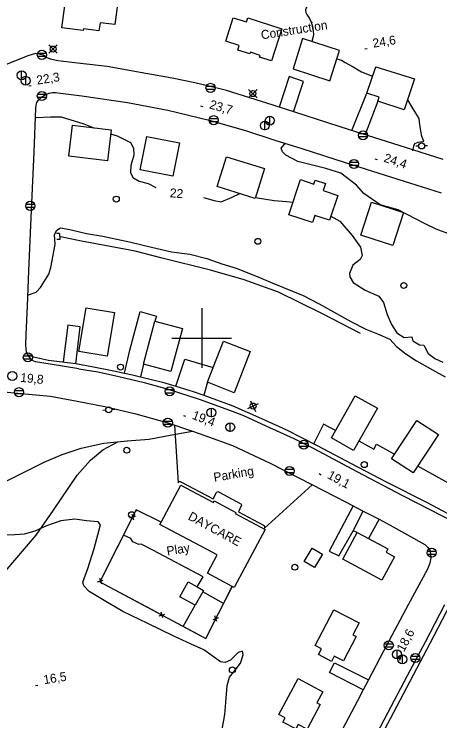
# Model space of a CAD drawing. Extents: x 646142 to 649934, y 5874075 to 5876351.
# Drawn here: x 647137.1 to 647279.9, y 5875071.6 to 5875308.6 of the extents above; entities that cross this region are included whole.
import ezdxf

# ---------------------------------------------------------------- set-up
doc = ezdxf.new("R2010")
doc.units = 0
for name, color, linetype in [('Niveau 1', 7, 'Continuous'), ('Niveau 19', 7, 'Continuous'), ('Niveau 2', 7, 'Continuous'), ('Niveau 21', 7, 'Continuous'), ('Niveau 22', 7, 'Continuous'), ('Niveau 26', 7, 'Continuous'), ('Niveau 3', 7, 'Continuous'), ('Niveau 31', 7, 'Continuous'), ('Niveau 36', 7, 'Continuous'), ('Niveau 37', 7, 'Continuous'), ('Niveau 4', 7, 'Continuous'), ('Niveau 52', 7, 'Continuous'), ('Niveau 56', 7, 'Continuous'), ('Niveau 61', 7, 'Continuous')]:
    doc.layers.add(name, color=color, linetype=linetype)

msp = doc.modelspace()

# ---------------------------------------------------------------- linework, layer by layer
at = {"layer": 'Niveau 1'}
msp.add_lwpolyline([(647141.45, 5875214.48), (647141.95, 5875214.49), (647144.48, 5875215.37), (647145.91, 5875216.98), (647148.71, 5875221.37), (647149.38, 5875223.68), (647150.8, 5875231.33), (647150.67, 5875234.68), (647151.43, 5875236.2), (647152.67, 5875236.92), (647155.81, 5875236.39), (647161.32, 5875235.07), (647166.84, 5875234.15), (647176.18, 5875232.21), (647183.16, 5875230.44), (647189.88, 5875228.93), (647196.07, 5875228.09), (647201.7, 5875226.72), (647206.79, 5875224.9), (647211.57, 5875223.43), (647218.59, 5875220.64), (647223.89, 5875218.44), (647234.08, 5875214.22), (647239.38, 5875211.51), (647250.03, 5875205.53), (647255.08, 5875202.96), (647259.01, 5875201.39), (647263.06, 5875199.61), (647265.31, 5875197.16), (647268.51, 5875194.66), (647272.04, 5875192.33), (647277.43, 5875189.34), (647281.7, 5875187.04)], dxfattribs=at)
at = {"layer": 'Niveau 19'}
for points in [[(647230.81, 5875275.89), (647234.09, 5875286.09), (647229.35, 5875287.67), (647225.99, 5875277.44)], [(647250.38, 5875269.62), (647255.44, 5875282.18)], [(647259.08, 5875279.41), (647254.81, 5875268.22)], [(647174.14, 5875188.23), (647175.91, 5875195.88), (647179.34, 5875208.88), (647184.82, 5875207.39), (647184.31, 5875205.69)], [(647157.82, 5875191.4), (647159.2, 5875203.8), (647155.14, 5875204.35), (647153.5, 5875191.98)], [(647191.36, 5875183.84), (647194.37, 5875192.95), (647203.83, 5875190.09)], [(647180.46, 5875191.25), (647179.48, 5875187)], [(647201.91, 5875185.15), (647200.76, 5875180.79)], [(647244.91, 5875168.99), (647240.82, 5875171.13), (647237.6, 5875164.59)], [(647252.71, 5875165.47), (647257.71, 5875162.74), (647258.59, 5875164.42), (647264.69, 5875161.07)], [(647272.44, 5875157.09), (647282.46, 5875151.51)], [(647250.81, 5875143.7), (647242.77, 5875128.47), (647245.97, 5875126.97), (647250.8, 5875135.36)], [(647252.13, 5875134.8), (647250.8, 5875135.36), (647254.2, 5875141.95)], [(647259.48, 5875139.23), (647256, 5875132.72)], [(647254.19, 5875082.02), (647242.92, 5875087.82), (647244.57, 5875091.09), (647255.97, 5875085.4)]]:
    msp.add_lwpolyline(points, dxfattribs=at)
at = {"layer": 'Niveau 2'}
for points in [[(647235.63, 5875311.32), (647235.08, 5875310.72), (647234.87, 5875310.03), (647234.95, 5875309.22), (647235.22, 5875308.48), (647236.17, 5875307.13), (647236.77, 5875305.99), (647237.06, 5875304.58), (647237.42, 5875302.98), (647237.54, 5875301.84), (647237.37, 5875301.19), (647236.92, 5875299.42)], [(647245.35, 5875293.67), (647246.84, 5875293.2), (647248.17, 5875292.47), (647250.79, 5875290.92), (647253.55, 5875289.32), (647257.34, 5875287.86)], [(647269.05, 5875279.88), (647270.46, 5875277.38), (647271.67, 5875275.44), (647272.78, 5875273.58), (647272.95, 5875272.39), (647273.23, 5875270.16), (647273.58, 5875268.13), (647273.85, 5875267.43), (647274.37, 5875266.09), (647274.16, 5875265.78), (647272.45, 5875265.56), (647271.39, 5875265.11), (647271.03, 5875264.4), (647270.72, 5875262.78)], [(647144.18, 5875274.06), (647144.42, 5875274.01), (647149.26, 5875274.23), (647152.85, 5875274.14), (647160.49, 5875271.9), (647163.83, 5875270.5)], [(647169.43, 5875268.52), (647171.61, 5875267.77), (647176.12, 5875265.55), (647177.11, 5875263.7), (647177.29, 5875261.36), (647176.2, 5875257.92), (647176.15, 5875255.56), (647176.9, 5875253.8), (647179.04, 5875252.64), (647182.08, 5875251.81), (647184.59, 5875250.44)], [(647283.47, 5875234.76), (647278.6, 5875236.51), (647274.73, 5875238.39), (647265.85, 5875242.95), (647259.86, 5875244.67), (647254.34, 5875248.51), (647251.93, 5875251.23), (647246.68, 5875255.27), (647241.61, 5875256.91), (647232.21, 5875259.25), (647228.19, 5875261.29), (647227.09, 5875262.5), (647226.68, 5875263.71), (647227.87, 5875265.1), (647228.22, 5875265.31)], [(647200.55, 5875247.17), (647204.22, 5875246.1), (647206.52, 5875245.71), (647210.18, 5875247.24), (647212.77, 5875248.44)], [(647218.05, 5875247.18), (647224.34, 5875246.08), (647228.47, 5875245.83), (647230.64, 5875245.62)], [(647243.37, 5875240.93), (647246.35, 5875239.16), (647250.52, 5875234.43), (647253.28, 5875230.53), (647253.85, 5875227.73), (647253.18, 5875226.39), (647250.71, 5875224.47), (647249.56, 5875221.6), (647249.67, 5875220.52), (647250.84, 5875218.64), (647254.85, 5875216.08), (647259.38, 5875214.03), (647260.98, 5875211.96), (647262.25, 5875207.86), (647263.68, 5875204.57), (647265.46, 5875201.72), (647267.87, 5875200.14), (647270.44, 5875200.46), (647270.81, 5875199.07), (647273.02, 5875197.76), (647274.54, 5875197.57), (647275.96, 5875194.86), (647278.22, 5875193.09), (647280.93, 5875191.89)], [(647206.29, 5875065.53), (647207.74, 5875073.69), (647208.15, 5875077.71), (647208.5, 5875083.51), (647209.33, 5875086.3), (647211.19, 5875088.62), (647212.98, 5875090.99), (647213.93, 5875093.73), (647213.69, 5875094.98), (647212.22, 5875094.54), (647209.63, 5875091.98), (647207.85, 5875091.17), (647206.32, 5875091.42), (647200.69, 5875095.42), (647196.43, 5875097.3), (647190.7, 5875100.02), (647181.98, 5875104.22), (647173.56, 5875108.29), (647167.27, 5875111.93), (647162.27, 5875114.94), (647160.45, 5875116.84), (647160.1, 5875118.07), (647161.79, 5875122.67), (647163.91, 5875129.39), (647166.08, 5875137.32), (647165.28, 5875138.33), (647161.35, 5875138.69), (647157.47, 5875139.23), (647152.77, 5875138.64), (647147.94, 5875137.02), (647143.99, 5875135.24), (647140.43, 5875134.26), (647137.32, 5875134.01), (647133.33, 5875133.9)]]:
    msp.add_lwpolyline(points, dxfattribs=at)
at = {"layer": 'Niveau 21'}
for points in [[(647280.95, 5875259.87), (647268.4, 5875263.92), (647249.6, 5875269.87), (647223.95, 5875278.09), (647208.28, 5875282.97), (647202, 5875284.58), (647197.71, 5875285.58), (647190.14, 5875287.11), (647181.3, 5875288.75), (647168.25, 5875291.06), (647159.33, 5875292.11), (647151.73, 5875292.97), (647149.26, 5875293.53), (647147.95, 5875294.12), (647146.9, 5875294.92), (647144.2, 5875295.46), (647141.73, 5875294.63), (647134.18, 5875291.64)], [(647158.78, 5875189.64), (647149.22, 5875191.26), (647144.27, 5875192.03), (647143.66, 5875192.25), (647142.91, 5875192.73), (647142.34, 5875193.42), (647141.57, 5875194.5), (647141.21, 5875195.4), (647141.07, 5875196.33), (647141.03, 5875197.68), (647141.15, 5875201.14), (647141.54, 5875210.69), (647142.04, 5875222.49), (647142.9, 5875242.92), (647143.77, 5875262.3), (647144.34, 5875277.13), (647144.48, 5875278.1), (647144.73, 5875278.97), (647145.16, 5875279.67), (647145.66, 5875280.2), (647146.39, 5875280.85), (647147.41, 5875281.51), (647148.25, 5875281.96), (647148.86, 5875282.14), (647149.97, 5875282.31), (647150.94, 5875282.31), (647152.66, 5875282.18), (647159.82, 5875281.25), (647175.1, 5875279.05), (647188.63, 5875276.48), (647202.51, 5875273.12), (647214.65, 5875269.56), (647224.54, 5875266.35), (647233.55, 5875263.52), (647245.04, 5875259.9), (647257.33, 5875255.99), (647269.75, 5875252.06), (647280.31, 5875248.67)], [(647158.78, 5875189.64), (647165.19, 5875188.63), (647171.81, 5875187.26), (647180.72, 5875185.09), (647188.7, 5875182.83), (647199.47, 5875179.37), (647210.17, 5875175.45), (647214.02, 5875174.01), (647221.54, 5875170.56), (647230.88, 5875166.26), (647237.58, 5875162.95), (647252, 5875155.29), (647267.38, 5875147.16), (647285.42, 5875137.94), (647296.39, 5875132.22), (647308.36, 5875125.81), (647322.73, 5875118.39), (647329.68, 5875114.76), (647338.75, 5875110.68), (647353.4, 5875105.02), (647362.11, 5875102.16), (647373.66, 5875098.57), (647386.89, 5875095.51)], [(647129.03, 5875182.41), (647139.45, 5875181.45), (647149.3, 5875180.46), (647158.27, 5875178.82), (647167.49, 5875177.08), (647177.91, 5875174.62), (647188.27, 5875171.72), (647196.92, 5875168.76), (647201.1, 5875167.33), (647210.35, 5875163.95), (647222.98, 5875158.05), (647236.89, 5875150.91), (647248.48, 5875144.9)], [(647248.48, 5875144.9), (647254.2, 5875141.95), (647259.48, 5875139.23), (647263.23, 5875137.29), (647274.88, 5875130.72), (647275.89, 5875129.79), (647276.59, 5875128.61), (647276.82, 5875126.34), (647276.54, 5875124.47), (647275.7, 5875122.44), (647269.27, 5875110.52), (647261, 5875094.98), (647255.97, 5875085.4), (647254.19, 5875082.02), (647252.27, 5875078.35), (647246.24, 5875066.95)], [(647404.42, 5874995.61), (647383.56, 5874999.21), (647359.7, 5875003.67), (647349.49, 5875005.67), (647330.62, 5875009.23), (647326.93, 5875010.02), (647321.05, 5875011.75), (647311.59, 5875015.56), (647297.2, 5875023.14), (647280.31, 5875032.56), (647266.62, 5875040.33), (647257.64, 5875045.21), (647254.67, 5875046.99), (647253.59, 5875048.5), (647252.7, 5875050.38), (647252.15, 5875052.4), (647252.44, 5875054.16), (647253.13, 5875056.53), (647257.52, 5875064.93), (647262.38, 5875074.29), (647269.02, 5875086.82), (647275.09, 5875098.14), (647281.6, 5875110.65)]]:
    msp.add_lwpolyline(points, dxfattribs=at)
at = {"layer": 'Niveau 22'}
for points in [[(647141.57, 5875194.5), (647143.63, 5875193.71), (647148.61, 5875192.63), (647157.77, 5875191.41), (647163.19, 5875190.49), (647169.93, 5875189.13), (647174.14, 5875188.23), (647176.79, 5875187.67), (647179.48, 5875187), (647186.89, 5875185.17), (647191.36, 5875183.84), (647197.15, 5875182.12), (647200.76, 5875180.79), (647210.49, 5875177.21), (647220.05, 5875173.05), (647228.18, 5875169.31), (647238.78, 5875164), (647250.15, 5875157.97), (647261.87, 5875151.75), (647275.39, 5875144.92), (647287.59, 5875138.52)], [(647133.12, 5875151.38), (647140.41, 5875155.06), (647147.15, 5875158.35), (647153.15, 5875160.89), (647159.52, 5875163.1), (647167.2, 5875164.73), (647174.95, 5875165.54), (647182.37, 5875166.1), (647189.93, 5875167.59), (647196.92, 5875168.76)], [(647046.91, 5875074.33), (647057.34, 5875080.28), (647062.95, 5875083.1), (647072.61, 5875087.23), (647091.51, 5875094.75), (647105.67, 5875100.32), (647110.9, 5875103.1), (647117.34, 5875107.37), (647126.43, 5875113.96), (647134.04, 5875121.74), (647144.5, 5875133.85), (647150.3, 5875142.29), (647158.18, 5875154.03), (647162.7, 5875159.04), (647166.79, 5875162.46), (647171.92, 5875165.22)], [(647257.93, 5875062.33), (647263.3, 5875072.43), (647269.94, 5875084.97), (647276.68, 5875097.62), (647282.12, 5875108.18), (647287.6, 5875118.28), (647286.71, 5875120.03)]]:
    msp.add_lwpolyline(points, dxfattribs=at)
at = {"layer": 'Niveau 26'}
for p, q in [((647152.33, 5875235.06), (647151.33, 5875235.04)), ((647152.33, 5875235.06), (647152.37, 5875233.04)), ((647152.37, 5875233.04), (647151.38, 5875233.02))]:
    msp.add_line(p, q, dxfattribs=at)
at = {"layer": 'Niveau 3'}
for p, q in [((647254.73, 5875296.96), (647255.52, 5875297.09)), ((647141.98, 5875284.57), (647142.77, 5875284.7)), ((647199.61, 5875277.9), (647200.37, 5875277.68)), ((647258.08, 5875260.14), (647258.84, 5875259.89)), ((647193.86, 5875174.04), (647194.61, 5875173.76)), ((647239.38, 5875154.55), (647240.08, 5875154.16)), ((647266.4, 5875092), (647266.78, 5875092.7)), ((647144.29, 5875083.49), (647145.08, 5875083.61))]:
    msp.add_line(p, q, dxfattribs=at)
at = {"layer": 'Niveau 31'}
for points in [[(647153.13, 5875304.08), (647155.83, 5875324.69), (647168.29, 5875323.05), (647167.14, 5875314.26), (647171.95, 5875313.62), (647170.83, 5875305.12), (647165.89, 5875305.77), (647165.52, 5875302.99), (647160.3, 5875303.67), (647160.23, 5875303.15), (647153.13, 5875304.08)], [(647226.89, 5875303.71), (647223.45, 5875292.96), (647219.42, 5875294.25), (647219.6, 5875294.8), (647216.33, 5875295.85), (647216.15, 5875295.27), (647212.09, 5875296.56), (647212.6, 5875298.14), (647208.05, 5875299.59), (647210.56, 5875307.45), (647215.04, 5875306.02), (647215.46, 5875307.36), (647226.89, 5875303.71)], [(647230.64, 5875290.33), (647242.93, 5875286.25), (647246.25, 5875296.43), (647233.82, 5875300.42), (647230.64, 5875290.33), (647230.64, 5875290.33)], [(647258.39, 5875290.99), (647271.35, 5875286.94), (647267.95, 5875276.52), (647259.08, 5875279.41), (647259.54, 5875280.78), (647255.44, 5875282.18), (647258.39, 5875290.99), (647258.39, 5875290.99)], [(647168.35, 5875259.46), (647155.39, 5875261.01), (647156.63, 5875271.36), (647169.59, 5875269.81), (647168.35, 5875259.46)], [(647190.34, 5875254.27), (647179.41, 5875256.44), (647181.63, 5875267.63), (647192.56, 5875265.46), (647190.34, 5875254.27)], [(647217.94, 5875246.82), (647205.17, 5875250.81), (647208.29, 5875260.8), (647221.06, 5875256.81), (647217.94, 5875246.82)], [(647229.22, 5875241.35), (647233.13, 5875253.12), (647237.66, 5875251.62), (647238.1, 5875252.95), (647241.48, 5875251.82), (647240.71, 5875249.49), (647245.67, 5875247.85), (647242.89, 5875239.49), (647237.97, 5875241.12), (647237.17, 5875238.71), (647229.22, 5875241.35)], [(647264.16, 5875231.04), (647253.37, 5875234.52), (647256.92, 5875245.54), (647267.71, 5875242.06), (647264.16, 5875231.04)], [(647158.79, 5875195.44), (647161.23, 5875210.13), (647170.73, 5875208.56), (647168.29, 5875193.87), (647158.79, 5875195.44)], [(647180.46, 5875191.25), (647184.31, 5875205.69), (647193.55, 5875203.23), (647189.7, 5875188.79), (647180.46, 5875191.25)], [(647201.91, 5875185.15), (647203.83, 5875190.09), (647207.27, 5875198.94), (647216.21, 5875195.47), (647210.85, 5875181.68), (647201.91, 5875185.15)], [(647243.5, 5875166.5), (647251.53, 5875180.67), (647258.94, 5875176.47), (647250.91, 5875162.3), (647243.5, 5875166.5)], [(647263.67, 5875159.53), (647272.18, 5875172.38), (647279.4, 5875167.6), (647270.89, 5875154.75), (647263.67, 5875159.53)], [(647205.19, 5875127.29), (647186.01, 5875137.5), (647186.44, 5875138.29), (647193.02, 5875150.67), (647203.95, 5875144.86), (647204.22, 5875145.35), (647211.43, 5875141.52), (647211.22, 5875141.11), (647221.25, 5875135.78), (647210.92, 5875116.37), (647210.27, 5875116.71), (647201.93, 5875121.15), (647205.19, 5875127.29)], [(647260.46, 5875118.78), (647247.32, 5875125.85), (647252.13, 5875134.8), (647256, 5875132.72), (647262.42, 5875129.27), (647261.83, 5875128.18), (647264.69, 5875126.64), (647260.46, 5875118.78)], [(647234.35, 5875125.1), (647237.01, 5875129.57), (647240.49, 5875127.49), (647237.83, 5875123.02), (647234.35, 5875125.1)], [(647195.47, 5875118.25), (647198.49, 5875116.55), (647200.61, 5875115.36), (647200.33, 5875114.86), (647197.8, 5875110.36), (647192.67, 5875113.24), (647195.47, 5875118.25)], [(647238.07, 5875096.88), (647244.33, 5875108.86), (647252.8, 5875104.44), (647250.74, 5875100.5), (647251.83, 5875099.94), (647247.52, 5875091.7), (647244.47, 5875093.29), (647243.57, 5875091.56), (647239.15, 5875093.87), (647240.15, 5875095.79), (647238.07, 5875096.88)], [(647225.92, 5875073.74), (647232.35, 5875085.8), (647240.64, 5875081.39), (647238.67, 5875077.69), (647239.78, 5875077.1), (647235.36, 5875068.81), (647232.33, 5875070.43), (647231.52, 5875068.92), (647227.24, 5875071.2), (647228, 5875072.63), (647225.92, 5875073.74)]]:
    msp.add_lwpolyline(points, dxfattribs=at)
at = {"layer": 'Niveau 36'}
for p, q in [((647151.56, 5875295.51), (647148.74, 5875298.33)), ((647148.74, 5875295.51), (647151.56, 5875298.33)), ((647147.82, 5875295.44), (647144.94, 5875295.44)), ((647144.94, 5875294.52), (647147.82, 5875294.52)), ((647139.61, 5875286.61), (647139.61, 5875289.61)), ((647140.96, 5875284.78), (647140.96, 5875287.78)), ((647204.4, 5875284.37), (647201.52, 5875284.37)), ((647201.52, 5875283.45), (647204.4, 5875283.45)), ((647218.57, 5875280.57), (647215.75, 5875283.39)), ((647215.75, 5875280.57), (647218.57, 5875283.39)), ((647147.82, 5875281.67), (647144.94, 5875281.67)), ((647144.94, 5875280.75), (647147.82, 5875280.75)), ((647205.47, 5875273.53), (647202.59, 5875273.53)), ((647202.59, 5875272.61), (647205.47, 5875272.61)), ((647221.18, 5875269.77), (647221.18, 5875272.77)), ((647222.85, 5875271.43), (647222.85, 5875274.43)), ((647255.55, 5875268.48), (647252.67, 5875268.48)), ((647252.67, 5875267.56), (647255.55, 5875267.56)), ((647271.78, 5875264.43), (647272.78, 5875264.43)), ((647275.78, 5875264.43), (647274.78, 5875264.43)), ((647252.5, 5875258.85), (647249.62, 5875258.85)), ((647249.62, 5875257.93), (647252.5, 5875257.93)), ((647143.94, 5875244.79), (647141.06, 5875244.79)), ((647141.06, 5875243.87), (647143.94, 5875243.87)), ((647143.13, 5875193.97), (647140.25, 5875193.97)), ((647140.25, 5875193.05), (647143.13, 5875193.05)), ((647190.69, 5875182.59), (647187.81, 5875182.59)), ((647140.14, 5875182.29), (647137.26, 5875182.29)), ((647137.26, 5875181.37), (647140.14, 5875181.37)), ((647187.81, 5875181.67), (647190.69, 5875181.67)), ((647215.44, 5875176.33), (647219.04, 5875178.05)), ((647216.39, 5875178.99), (647218.1, 5875175.39)), ((647166.81, 5875175.83), (647167.81, 5875175.88)), ((647170.81, 5875176.02), (647169.81, 5875175.98)), ((647203.24, 5875173.51), (647203.24, 5875176.51)), ((647190.08, 5875172.03), (647187.2, 5875172.03)), ((647187.2, 5875171.11), (647190.08, 5875171.11)), ((647209.57, 5875168.6), (647209.57, 5875171.6)), ((647235.68, 5875164.66), (647232.8, 5875164.66)), ((647232.8, 5875163.74), (647235.68, 5875163.74)), ((647230.9, 5875155.87), (647228.02, 5875155.87)), ((647228.02, 5875154.95), (647230.9, 5875154.95)), ((647278.59, 5875128.46), (647275.71, 5875128.46)), ((647275.71, 5875127.54), (647278.59, 5875127.54)), ((647264.2, 5875097.36), (647261.32, 5875097.36)), ((647261.32, 5875096.44), (647264.2, 5875096.44)), ((647265.52, 5875092.38), (647265.52, 5875095.38)), ((647267.31, 5875090.72), (647267.31, 5875093.72)), ((647273.1, 5875093.17), (647270.22, 5875093.17)), ((647270.22, 5875092.25), (647273.1, 5875092.25))]:
    msp.add_line(p, q, dxfattribs=at)
for centre, radius in [((647146.38, 5875294.99), 1.52), ((647150.15, 5875296.93), 1), ((647139.6, 5875288.12), 1.5), ((647140.95, 5875286.28), 1.5), ((647202.96, 5875283.91), 1.52), ((647146.38, 5875281.21), 1.52), ((647217.17, 5875281.98), 1), ((647204.03, 5875273.07), 1.52), ((647221.17, 5875271.28), 1.5), ((647222.84, 5875272.94), 1.5), ((647254.11, 5875268.02), 1.52), ((647273.78, 5875264.43), 1), ((647251.06, 5875258.4), 1.52), ((647171.35, 5875246.6), 1), ((647142.5, 5875244.34), 1.52), ((647218.83, 5875232.44), 1), ((647267.78, 5875217.64), 1), ((647141.69, 5875193.51), 1.52), ((647172.77, 5875190.26), 1), ((647136.45, 5875187.26), 1.5), ((647138.7, 5875181.84), 1.52), ((647189.25, 5875182.14), 1.52), ((647217.25, 5875177.19), 1), ((647168.81, 5875175.93), 1), ((647203.23, 5875175.02), 1.5), ((647188.64, 5875171.58), 1.52), ((647209.56, 5875170.11), 1.5), ((647234.24, 5875164.21), 1.52), ((647174.87, 5875162.37), 1), ((647229.46, 5875155.42), 1.52), ((647254.53, 5875157.54), 1), ((647176.47, 5875140.76), 1), ((647277.15, 5875128.01), 1.52), ((647231.22, 5875123.13), 1), ((647262.76, 5875096.91), 1.52), ((647265.51, 5875093.89), 1.5), ((647267.3, 5875092.23), 1.5), ((647271.66, 5875092.72), 1.52), ((647210.29, 5875088.7), 1)]:
    msp.add_circle(centre, radius, dxfattribs=at)
at = {"layer": 'Niveau 37'}
for points in [[(647186.44, 5875138.29), (647178.05, 5875142.36), (647165.86, 5875118.18), (647201.35, 5875099.28), (647210.27, 5875116.71)], [(647186.44, 5875138.29), (647178.05, 5875142.36), (647165.86, 5875118.18), (647201.35, 5875099.28), (647210.27, 5875116.71)], [(647186.44, 5875138.29), (647178.05, 5875142.36), (647165.86, 5875118.18), (647201.35, 5875099.28), (647210.27, 5875116.71)], [(647186.44, 5875138.29), (647178.05, 5875142.36), (647177.74, 5875141.76)], [(647175.89, 5875139.66), (647177.79, 5875140.28)], [(647176.53, 5875140.92), (647177.16, 5875139.02)], [(647175.94, 5875138.18), (647171.44, 5875129.25)], [(647171.44, 5875129.25), (647166.94, 5875120.32)], [(647165.09, 5875118.22), (647166.99, 5875118.85)], [(647165.73, 5875119.49), (647166.35, 5875117.59)], [(647167.26, 5875117.43), (647176.09, 5875112.73)], [(647205.62, 5875107.63), (647210.18, 5875116.53)], [(647210.18, 5875116.53), (647210.27, 5875116.71)], [(647176.09, 5875112.73), (647184.92, 5875108.03)], [(647193.82, 5875103.28), (647197.8, 5875110.36)], [(647193.82, 5875103.28), (647197.8, 5875110.36)], [(647193.82, 5875103.28), (647197.8, 5875110.36)], [(647193.82, 5875103.28), (647197.8, 5875110.36)], [(647185.72, 5875106.79), (647187.64, 5875107.38)], [(647186.97, 5875106.13), (647186.39, 5875108.04)], [(647205.02, 5875104.89), (647204.4, 5875106.8)], [(647188.45, 5875106.15), (647197.27, 5875101.45)], [(647205.67, 5875106.15), (647203.76, 5875105.54)], [(647197.27, 5875101.45), (647201.35, 5875099.28), (647203.8, 5875104.07)]]:
    msp.add_lwpolyline(points, dxfattribs=at)
at = {"layer": 'Niveau 4'}
msp.add_lwpolyline([(647253.23, 5875201.53), (647240.56, 5875208.14), (647225.75, 5875215.41), (647214.22, 5875219.48), (647202.96, 5875222.77), (647186.79, 5875226.84), (647177.71, 5875229.1), (647167.51, 5875231.04), (647159.68, 5875232.45), (647152.63, 5875233.9)], dxfattribs=at)
at = {"layer": 'Niveau 52'}
msp.add_lwpolyline([(647190.87, 5875170.83), (647192.12, 5875151.45), (647192.35, 5875151.77), (647192.59, 5875151.86), (647192.73, 5875151.85), (647193, 5875151.83), (647203.83, 5875146.09), (647204.94, 5875148.21), (647205.14, 5875148.4), (647205.42, 5875148.48), (647205.59, 5875148.47), (647205.87, 5875148.33), (647213.09, 5875144.44), (647213.27, 5875144.26), (647213.34, 5875144.05), (647213.32, 5875143.81), (647213.28, 5875143.68), (647212.31, 5875141.7), (647220.78, 5875137.28), (647221.02, 5875137.04), (647221.08, 5875136.76), (647221.04, 5875136.44), (647221.01, 5875136.27), (647237.09, 5875150.8)], dxfattribs=at)
at = {"layer": 'Niveau 56'}
for points in [[(647198.49, 5875116.55), (647200.48, 5875119.86), (647183.57, 5875128.88), (647179.66, 5875130.91), (647178.87, 5875130.71), (647176.92, 5875131.67), (647176.23, 5875132.75), (647173.76, 5875133.86)], [(647207.33, 5875110.96), (647200.33, 5875114.86)]]:
    msp.add_lwpolyline(points, dxfattribs=at)
at = {"layer": 'Niveau 61'}
for points in [[(647200, 5875210), (647200, 5875200), (647200, 5875190)], [(647190, 5875200), (647200, 5875200), (647210, 5875200)]]:
    msp.add_lwpolyline(points, dxfattribs=at)

# ---------------------------------------------------------------- texts
at = {"layer": 'Niveau 2'}
msp.add_text('22', height=3, rotation=355.3665, dxfattribs=at).set_placement((647189.22, 5875247.25))
at = {"layer": 'Niveau 3'}
for s, rotation, p in [('24,6 ', 8.9405, (647257.58, 5875297.37)), ('22,3 ', 8.9405, (647144.83, 5875284.98)), ('23,7 ', 343.9857, (647202.36, 5875277.07)), ('24,4 ', 341.6166, (647260.81, 5875259.2)), ('19,8 ', 354.4811, (647139.05, 5875185.33)), ('19,4 ', 339.2247, (647196.54, 5875172.98)), ('19,1 ', 331.5245, (647241.89, 5875153.14)), ('18,6 ', 61.5552, (647267.81, 5875094.51)), ('16,5 ', 8.9405, (647147.14, 5875083.89))]:
    msp.add_text(s, height=3, rotation=rotation, dxfattribs=at).set_placement(p)
at = {"layer": 'Niveau 31'}
for s, rotation, p in [('Construction', 8.9405, (647220.11, 5875300.13)), ('DAYCARE', 331.54, (647195.16, 5875139.29))]:
    msp.add_text(s, height=3, rotation=rotation, dxfattribs=at).set_placement(p)
at = {"layer": 'Niveau 52'}
msp.add_text('Parking', height=3, rotation=9.6211, dxfattribs=at).set_placement((647204.25, 5875151.79))
at = {"layer": 'Niveau 56'}
msp.add_text('Play', height=3, rotation=8.9405, dxfattribs=at).set_placement((647188.48, 5875127.04))

doc.saveas('drawing.dxf')
